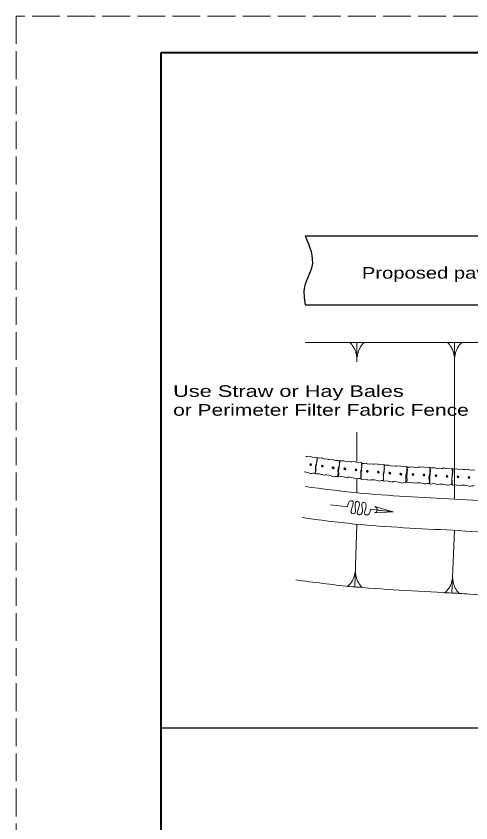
# Model space of a CAD drawing. Extents: x 1043.1 to 1101.1, y 672.4 to 716.4.
# Drawn here: x 1043.14 to 1049.41, y 705.27 to 716.4 of the extents above; entities that cross this region are included whole.
import ezdxf

# ---------------------------------------------------------------- set-up
doc = ezdxf.new("R2010")
doc.units = 0
doc.header["$LTSCALE"] = 0.064
doc.linetypes.add('LONG_DASHED', pattern=[7.5, 6, -1.5])
doc.layers.add('1', color=7, linetype='Continuous', lineweight=13)

msp = doc.modelspace()

# ---------------------------------------------------------------- hatches: boundary and pattern name
at = {"layer": '1'}
for points in [[(1047.19383, 710.21342), (1047.19858, 710.20108), (1047.21058, 710.1995), (1047.21775, 710.21008), (1047.213, 710.22242), (1047.20083, 710.22392)], [(1047.35325, 710.19408), (1047.35783, 710.18183), (1047.36983, 710.17992), (1047.37733, 710.1905), (1047.37283, 710.20275), (1047.36083, 710.2045)], [(1047.5045, 710.17092), (1047.509, 710.15875), (1047.521, 710.15675), (1047.52858, 710.16733), (1047.52408, 710.1795), (1047.51208, 710.18133)], [(1047.66525, 710.15583), (1047.67042, 710.14383), (1047.6825, 710.14258), (1047.68942, 710.15358), (1047.68433, 710.1655), (1047.67217, 710.16675)], [(1047.81733, 710.14108), (1047.8225, 710.12933), (1047.83467, 710.12808), (1047.8415, 710.13892), (1047.8365, 710.151), (1047.82442, 710.15225)], [(1047.97525, 710.11942), (1047.98075, 710.1075), (1047.99275, 710.10683), (1047.9995, 710.11792), (1047.99408, 710.12992), (1047.982, 710.13058)], [(1048.12767, 710.10975), (1048.13317, 710.09775), (1048.14525, 710.097), (1048.15192, 710.108), (1048.1465, 710.11992), (1048.13442, 710.12075)], [(1048.28508, 710.09542), (1048.29042, 710.08333), (1048.30242, 710.0825), (1048.30933, 710.09333), (1048.30417, 710.10542), (1048.29208, 710.10633)], [(1048.43742, 710.08175), (1048.44267, 710.06992), (1048.45483, 710.06875), (1048.4615, 710.0795), (1048.4565, 710.0915), (1048.44425, 710.09275)], [(1048.605, 710.07708), (1048.6105, 710.06525), (1048.6225, 710.06475), (1048.629, 710.07592), (1048.62367, 710.08758), (1048.61158, 710.08825)], [(1048.75758, 710.06883), (1048.76308, 710.05692), (1048.77542, 710.05625), (1048.78175, 710.06725), (1048.77625, 710.07908), (1048.76408, 710.07983)], [(1048.92117, 710.05933), (1048.92667, 710.04733), (1048.93883, 710.04675), (1048.9455, 710.05758), (1048.93983, 710.06958), (1048.92775, 710.07025)], [(1049.07383, 710.05092), (1049.0795, 710.03908), (1049.09158, 710.03842), (1049.09817, 710.04958), (1049.09267, 710.06125), (1049.08042, 710.06225)], [(1049.22533, 710.04492), (1049.23075, 710.03292), (1049.24283, 710.03225), (1049.24942, 710.0435), (1049.244, 710.05525), (1049.23192, 710.05592)], [(1049.37783, 710.03575), (1049.38325, 710.02383), (1049.39533, 710.02308), (1049.40217, 710.03425), (1049.39658, 710.04608), (1049.3845, 710.04683)]]:
    msp.add_hatch(color=256, dxfattribs=at).paths.add_polyline_path(points)

# ---------------------------------------------------------------- linework, layer by layer
at = {"layer": '1', "lineweight": 25}
for p, q in [((1045.14425, 715.89508), (1076.64425, 715.89508)), ((1047.132, 713.36458), (1056.394, 713.36458)), ((1047.132, 712.41483), (1056.394, 712.41483)), ((1045.14425, 706.58517), (1075.64425, 706.58517))]:
    msp.add_line(p, q, dxfattribs=at)
at = {"layer": '1', "lineweight": 40}
msp.add_line((1045.14425, 715.89508), (1076.64425, 715.89508), dxfattribs=at)
at = {"layer": '1'}
for p, q in [((1047.132, 711.89675), (1056.394, 711.89675)), ((1047.74558, 711.89675), (1047.94333, 711.89675)), ((1047.84433, 711.62992), (1047.84433, 711.89675)), ((1049.09133, 711.89675), (1049.28917, 711.89675)), ((1049.19017, 710.953), (1049.19017, 711.89675)), ((1049.19017, 710.6015), (1049.19017, 711.00958)), ((1047.84433, 710.6015), (1047.84433, 710.65908)), ((1047.84433, 710.25975), (1047.84433, 710.6015)), ((1049.19017, 709.73792), (1049.19017, 710.6015)), ((1047.84433, 709.82425), (1047.84433, 710.01992)), ((1047.71492, 709.63208), (1047.4785, 709.6585)), ((1048.34467, 709.56142), (1048.02975, 709.59675)), ((1048.12325, 709.58633), (1048.34467, 709.56142)), ((1048.18717, 709.57908), (1048.34467, 709.56142)), ((1047.84433, 709.3915), (1047.81342, 708.528)), ((1049.19017, 709.3055), (1049.1545, 708.44183)), ((1047.91217, 708.52383), (1047.71467, 708.53225)), ((1047.91217, 708.52383), (1047.71467, 708.53225)), ((1049.25325, 708.43692), (1049.05567, 708.44675)), ((1049.39583, 708.42725), (1050.39842, 708.363))]:
    msp.add_line(p, q, dxfattribs=at)
at = {"layer": '1', "linetype": 'LONG_DASHED'}
msp.add_lwpolyline([(1043.14425, 694.39508), (1077.14425, 694.39508), (1077.14425, 716.39508), (1043.14425, 716.39508)], close=True, dxfattribs=at)
at = {"layer": '1', "lineweight": 25}
msp.add_lwpolyline([(1076.64425, 694.89508), (1045.14425, 694.89508), (1045.14425, 715.89508)], dxfattribs=at)
at = {"layer": '1', "lineweight": 40}
msp.add_lwpolyline([(1045.14425, 715.89508), (1076.64425, 715.89508), (1076.64425, 694.89508), (1045.14425, 694.89508)], close=True, dxfattribs=at)
msp.add_lwpolyline([(1076.64425, 694.89508), (1045.14425, 694.89508), (1045.14425, 715.89508)], dxfattribs=at)
at = {"layer": '1'}
for points in [[(1047.13725, 710.32508), (1047.15458, 710.32442), (1047.16742, 710.33075), (1047.19683, 710.32208), (1047.2065, 710.3235), (1047.23433, 710.31275), (1047.27742, 710.31475), (1047.29317, 710.30492)], [(1047.26783, 710.09633), (1047.27642, 710.11775), (1047.27833, 710.17608), (1047.28842, 710.2145), (1047.28825, 710.2275), (1047.29692, 710.26775), (1047.29317, 710.285), (1047.29508, 710.30825)], [(1047.29317, 710.30492), (1047.28975, 710.26133), (1047.28458, 710.2275), (1047.274, 710.1975), (1047.27067, 710.17158), (1047.27367, 710.14175), (1047.27308, 710.11675), (1047.27008, 710.09283)], [(1047.29508, 710.30792), (1047.31267, 710.306), (1047.33225, 710.30358), (1047.35817, 710.30483), (1047.37183, 710.29758), (1047.39925, 710.28858), (1047.42625, 710.29133), (1047.45042, 710.28425)], [(1047.45042, 710.28425), (1047.4675, 710.283), (1047.48067, 710.28908), (1047.50958, 710.27975), (1047.51942, 710.28083), (1047.54717, 710.2695), (1047.59025, 710.2705), (1047.60583, 710.26042)], [(1047.60583, 710.26042), (1047.60142, 710.21658), (1047.59575, 710.18308), (1047.58467, 710.15333), (1047.58058, 710.12733), (1047.58317, 710.09758), (1047.58208, 710.0725), (1047.57867, 710.04875)], [(1047.58467, 710.05333), (1047.59208, 710.07508), (1047.59125, 710.13358), (1047.5995, 710.1725), (1047.59858, 710.1855), (1047.6055, 710.22608), (1047.60108, 710.24308), (1047.60183, 710.26675)], [(1047.60183, 710.26625), (1047.61933, 710.26525), (1047.639, 710.26392), (1047.66492, 710.26675), (1047.679, 710.26025), (1047.70642, 710.253), (1047.73333, 710.25692), (1047.75792, 710.25125)], [(1047.75792, 710.25125), (1047.77508, 710.25108), (1047.78783, 710.25783), (1047.81733, 710.25025), (1047.82692, 710.25192), (1047.85533, 710.24225), (1047.89833, 710.2455), (1047.91433, 710.23642)], [(1047.91433, 710.23642), (1047.91208, 710.1925), (1047.908, 710.15875), (1047.89825, 710.12825), (1047.8955, 710.102), (1047.89933, 710.07242), (1047.89958, 710.0475), (1047.89717, 710.0235)], [(1047.89733, 710.01475), (1047.90433, 710.03675), (1047.90175, 710.09492), (1047.90925, 710.13425), (1047.908, 710.14733), (1047.91367, 710.18783), (1047.90883, 710.20492), (1047.90892, 710.22833)], [(1047.90892, 710.22792), (1047.92667, 710.22742), (1047.94633, 710.22675), (1047.97208, 710.23033), (1047.98625, 710.22425), (1048.01392, 710.21783), (1048.04092, 710.22275), (1048.06533, 710.21783)], [(1048.06533, 710.21783), (1048.0825, 710.21808), (1048.09508, 710.22533), (1048.12483, 710.2185), (1048.13458, 710.22058), (1048.163, 710.21158), (1048.20592, 710.21642), (1048.22225, 710.20775)], [(1048.20517, 709.9925), (1048.21233, 710.01475), (1048.21158, 710.07325), (1048.21925, 710.112), (1048.21833, 710.12492), (1048.22508, 710.16542), (1048.22075, 710.18275), (1048.22158, 710.20625)], [(1048.22225, 710.20775), (1048.22108, 710.16383), (1048.21783, 710.12992), (1048.20892, 710.099), (1048.20675, 710.073), (1048.21158, 710.0435), (1048.21233, 710.0185), (1048.21058, 709.99433)], [(1048.2215, 710.20583), (1048.23883, 710.20475), (1048.25858, 710.20383), (1048.28425, 710.20642), (1048.29833, 710.19992), (1048.32617, 710.19258), (1048.35258, 710.19692), (1048.37742, 710.19142)], [(1048.37742, 710.19142), (1048.39475, 710.19133), (1048.40708, 710.198), (1048.43683, 710.19058), (1048.44658, 710.19258), (1048.47483, 710.18283), (1048.518, 710.18633), (1048.53392, 710.17708)], [(1047.27008, 710.09283), (1047.2355, 710.09275), (1047.21533, 710.0885), (1047.20075, 710.09133), (1047.18217, 710.09792), (1047.146, 710.10875), (1047.11442, 710.11292)], [(1047.4235, 710.07242), (1047.40642, 710.0735), (1047.39325, 710.06758), (1047.36417, 710.07692), (1047.35433, 710.07558), (1047.32642, 710.08708), (1047.28325, 710.08625), (1047.26783, 710.09633)], [(1048.53392, 710.17708), (1048.53175, 710.13325), (1048.528, 710.09942), (1048.51817, 710.06892), (1048.51583, 710.04292), (1048.51975, 710.0135), (1048.52017, 709.9885), (1048.51775, 709.9645)], [(1048.528, 709.9715), (1048.5345, 709.99383), (1048.532, 710.0525), (1048.53867, 710.09133), (1048.53733, 710.10425), (1048.543, 710.145), (1048.538, 710.162), (1048.53825, 710.1855)], [(1048.54192, 710.17592), (1048.5595, 710.17608), (1048.57925, 710.17683), (1048.60458, 710.18125), (1048.61925, 710.17592), (1048.64733, 710.1705), (1048.67358, 710.177), (1048.69858, 710.17342)], [(1048.69433, 710.17633), (1048.71167, 710.17683), (1048.72392, 710.184), (1048.75367, 710.1775), (1048.7635, 710.17983), (1048.792, 710.171), (1048.835, 710.17608), (1048.85125, 710.1675)], [(1048.85125, 710.1675), (1048.85042, 710.1235), (1048.84758, 710.08975), (1048.83875, 710.05875), (1048.837, 710.03275), (1048.84192, 710.00342), (1048.843, 709.97842), (1048.84133, 709.95433)], [(1048.84425, 709.9535), (1048.85108, 709.9755), (1048.84808, 710.03392), (1048.85517, 710.07308), (1048.85367, 710.08608), (1048.85908, 710.127), (1048.85408, 710.14383), (1048.85408, 710.16733)], [(1048.85408, 710.16683), (1048.87175, 710.16658), (1048.89142, 710.16608), (1048.91708, 710.16983), (1048.93125, 710.16392), (1048.95917, 710.15775), (1048.986, 710.163), (1049.01058, 710.15833)], [(1049.01058, 710.15833), (1049.02775, 710.15883), (1049.04017, 710.16608), (1049.07025, 710.15958), (1049.07967, 710.16183), (1049.10825, 710.15308), (1049.15117, 710.15833), (1049.1675, 710.14983)], [(1049.14783, 709.93942), (1049.15467, 709.96158), (1049.15183, 710.01992), (1049.159, 710.05892), (1049.15775, 710.072), (1049.16342, 710.11283), (1049.15842, 710.12958), (1049.15867, 710.15333)], [(1049.1675, 710.14983), (1049.16675, 710.10575), (1049.16375, 710.07183), (1049.155, 710.04108), (1049.15317, 710.015), (1049.15825, 709.9855), (1049.15933, 709.96042), (1049.15767, 709.93633)], [(1049.15867, 710.15292), (1049.17608, 710.15242), (1049.19583, 710.15183), (1049.22158, 710.15542), (1049.23583, 710.14942), (1049.26375, 710.14325), (1049.29042, 710.14825), (1049.31508, 710.14333)], [(1049.31508, 710.14333), (1049.33233, 710.14383), (1049.34483, 710.151), (1049.37458, 710.1445), (1049.38417, 710.1465), (1049.41275, 710.13783), (1049.45567, 710.14258), (1049.47183, 710.13392)], [(1047.57867, 710.04875), (1047.544, 710.04958), (1047.52383, 710.04592), (1047.50908, 710.049), (1047.49067, 710.05608), (1047.45475, 710.06758), (1047.4235, 710.07242)], [(1047.74117, 710.03842), (1047.72392, 710.0385), (1047.71125, 710.03175), (1047.68158, 710.03958), (1047.67183, 710.03783), (1047.64358, 710.04783), (1047.60067, 710.04425), (1047.58467, 710.05333)], [(1047.89717, 710.0235), (1047.86258, 710.02233), (1047.84275, 710.01733), (1047.82783, 710.01983), (1047.80908, 710.02583), (1047.77267, 710.03533), (1047.74117, 710.03842)], [(1048.054, 710.00433), (1048.037, 710.00408), (1048.02442, 709.997), (1047.99458, 710.00392), (1047.985, 710.00175), (1047.9565, 710.01075), (1047.9135, 710.00583), (1047.89733, 710.01475)], [(1048.21058, 709.99433), (1048.17608, 709.99208), (1048.15625, 709.98658), (1048.14133, 709.9885), (1048.1225, 709.994), (1048.08575, 710.00242), (1048.054, 710.00433)], [(1048.3615, 709.97842), (1048.34442, 709.97875), (1048.33167, 709.97192), (1048.30217, 709.97908), (1048.29225, 709.97758), (1048.264, 709.98733), (1048.22092, 709.98383), (1048.20517, 709.9925)], [(1048.51775, 709.9645), (1048.48325, 709.96283), (1048.46317, 709.95808), (1048.44825, 709.96033), (1048.4295, 709.96642), (1048.39283, 709.9755), (1048.3615, 709.97842)], [(1048.68475, 709.96292), (1048.66775, 709.96233), (1048.65508, 709.95533), (1048.62533, 709.9615), (1048.6155, 709.95958), (1048.58708, 709.96825), (1048.544, 709.96333), (1048.528, 709.9715)], [(1048.84133, 709.95433), (1048.807, 709.95142), (1048.78708, 709.946), (1048.772, 709.94783), (1048.753, 709.95308), (1048.71608, 709.961), (1048.68475, 709.96292)], [(1049.00108, 709.94492), (1048.98383, 709.94433), (1048.97142, 709.93708), (1048.94158, 709.94358), (1048.93192, 709.9415), (1048.90333, 709.95008), (1048.86042, 709.94492), (1048.84425, 709.9535)], [(1049.15767, 709.93633), (1049.12317, 709.93375), (1049.10342, 709.928), (1049.0885, 709.92983), (1049.06958, 709.93508), (1049.03275, 709.94308), (1049.00108, 709.94492)], [(1049.30458, 709.93008), (1049.28742, 709.92975), (1049.27492, 709.9225), (1049.24517, 709.92908), (1049.23542, 709.92692), (1049.20683, 709.93583), (1049.16392, 709.93083), (1049.14783, 709.93942)], [(1049.461, 709.92058), (1049.42675, 709.91833), (1049.40683, 709.91275), (1049.392, 709.91458), (1049.37292, 709.91992), (1049.33617, 709.928), (1049.30458, 709.93008)], [(1048.09283, 709.63325), (1048.34467, 709.56142), (1048.08467, 709.54708), (1048.08483, 709.54708)]]:
    msp.add_lwpolyline(points, dxfattribs=at)
for points in [[(1047.19383, 710.21342), (1047.19858, 710.20108), (1047.21058, 710.1995), (1047.21775, 710.21008), (1047.213, 710.22242), (1047.20083, 710.22392)], [(1047.35325, 710.19408), (1047.35783, 710.18183), (1047.36983, 710.17992), (1047.37733, 710.1905), (1047.37283, 710.20275), (1047.36083, 710.2045)], [(1047.5045, 710.17092), (1047.509, 710.15875), (1047.521, 710.15675), (1047.52858, 710.16733), (1047.52408, 710.1795), (1047.51208, 710.18133)], [(1047.66525, 710.15583), (1047.67042, 710.14383), (1047.6825, 710.14258), (1047.68942, 710.15358), (1047.68433, 710.1655), (1047.67217, 710.16675)], [(1047.81733, 710.14108), (1047.8225, 710.12933), (1047.83467, 710.12808), (1047.8415, 710.13892), (1047.8365, 710.151), (1047.82442, 710.15225)], [(1047.97525, 710.11942), (1047.98075, 710.1075), (1047.99275, 710.10683), (1047.9995, 710.11792), (1047.99408, 710.12992), (1047.982, 710.13058)], [(1048.12767, 710.10975), (1048.13317, 710.09775), (1048.14525, 710.097), (1048.15192, 710.108), (1048.1465, 710.11992), (1048.13442, 710.12075)], [(1048.28508, 710.09542), (1048.29042, 710.08333), (1048.30242, 710.0825), (1048.30933, 710.09333), (1048.30417, 710.10542), (1048.29208, 710.10633)], [(1048.43742, 710.08175), (1048.44267, 710.06992), (1048.45483, 710.06875), (1048.4615, 710.0795), (1048.4565, 710.0915), (1048.44425, 710.09275)], [(1048.605, 710.07708), (1048.6105, 710.06525), (1048.6225, 710.06475), (1048.629, 710.07592), (1048.62367, 710.08758), (1048.61158, 710.08825)], [(1048.75758, 710.06883), (1048.76308, 710.05692), (1048.77542, 710.05625), (1048.78175, 710.06725), (1048.77625, 710.07908), (1048.76408, 710.07983)], [(1048.92117, 710.05933), (1048.92667, 710.04733), (1048.93883, 710.04675), (1048.9455, 710.05758), (1048.93983, 710.06958), (1048.92775, 710.07025)], [(1049.07383, 710.05092), (1049.0795, 710.03908), (1049.09158, 710.03842), (1049.09817, 710.04958), (1049.09267, 710.06125), (1049.08042, 710.06225)], [(1049.22533, 710.04492), (1049.23075, 710.03292), (1049.24283, 710.03225), (1049.24942, 710.0435), (1049.244, 710.05525), (1049.23192, 710.05592)], [(1049.37783, 710.03575), (1049.38325, 710.02383), (1049.39533, 710.02308), (1049.40217, 710.03425), (1049.39658, 710.04608), (1049.3845, 710.04683)]]:
    msp.add_lwpolyline(points, close=True, dxfattribs=at)
msp.add_ellipse((1048.06804, 709.59252), major_axis=(0.05495, -0.00848), ratio=0.836798, start_param=5.14737274, end_param=7.51798588, dxfattribs=at)
at = {"layer": '1', "lineweight": 25}
msp.add_spline([(1047.132, 713.36458), (1047.22167, 712.94), (1047.12117, 712.6655), (1047.132, 712.41483)], degree=3, dxfattribs=at)
at = {"layer": '1'}
for points in [[(1047.84433, 711.68092), (1047.83242, 711.74358), (1047.81917, 711.78875), (1047.79583, 711.836), (1047.74558, 711.89675)], [(1047.94333, 711.89675), (1047.89292, 711.836), (1047.86967, 711.78875), (1047.85625, 711.74358), (1047.84433, 711.68092)], [(1049.19017, 711.68092), (1049.1785, 711.74358), (1049.165, 711.78875), (1049.14175, 711.836), (1049.09133, 711.89675)], [(1049.28917, 711.89675), (1049.23867, 711.836), (1049.21542, 711.78875), (1049.20192, 711.74358), (1049.19017, 711.68092)], [(1047.132, 709.91058), (1047.84433, 709.82425), (1049.19017, 709.73792), (1050.53608, 709.6515), (1051.88183, 709.56508), (1053.22758, 709.39258), (1053.76308, 709.23083)], [(1048.02975, 709.59675), (1047.99542, 709.52158), (1047.96217, 709.52042), (1047.95767, 709.68433), (1047.92775, 709.6915), (1047.90342, 709.53083), (1047.86042, 709.524), (1047.8635, 709.70092), (1047.83675, 709.70275), (1047.80575, 709.53692), (1047.77525, 709.5395), (1047.78158, 709.71192), (1047.75492, 709.71383), (1047.71492, 709.63208)], [(1047.08833, 709.4815), (1047.81092, 709.394), (1049.167, 709.30692), (1050.51275, 709.22058), (1051.84692, 709.13492), (1053.14792, 708.968), (1053.9465, 708.70742)], [(1047.71467, 708.53225), (1047.76717, 708.5905), (1047.79208, 708.63692), (1047.80708, 708.6815), (1047.82117, 708.74358)], [(1047.71467, 708.53225), (1047.76717, 708.5905), (1047.79208, 708.63692), (1047.80708, 708.6815), (1047.82117, 708.74358)], [(1047.82117, 708.74358), (1047.83083, 708.6805), (1047.84233, 708.63483), (1047.86408, 708.58633), (1047.91217, 708.52383)], [(1047.82117, 708.74358), (1047.83083, 708.6805), (1047.84233, 708.63483), (1047.86408, 708.58633), (1047.91217, 708.52383)], [(1049.05567, 708.44675), (1049.10842, 708.50483), (1049.13375, 708.551), (1049.149, 708.59533), (1049.16342, 708.6575)], [(1049.16342, 708.6575), (1049.17258, 708.59425), (1049.18408, 708.5485), (1049.2055, 708.5), (1049.25325, 708.43692)], [(1047.00083, 708.62333), (1047.74392, 708.53333), (1049.12058, 708.44483), (1049.39583, 708.42725)]]:
    msp.add_spline(points, degree=3, dxfattribs=at)

# ---------------------------------------------------------------- texts
for s, width, p in [('Proposed pavement', 1.3, (1047.91242, 712.77608)), ('Use Straw or Hay Bales ', 1.4, (1045.30958, 711.14642)), ('or Perimeter Filter Fabric Fence ', 1.35, (1045.30958, 710.88642))]:
    msp.add_text(s, height=0.16, dxfattribs=dict(at, width=width)).set_placement(p)

doc.saveas('drawing.dxf')
